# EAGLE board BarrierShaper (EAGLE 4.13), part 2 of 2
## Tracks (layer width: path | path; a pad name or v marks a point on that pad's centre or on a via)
+1.5V  (via drill 0.51, 0.71)
  Top 0.203: 100.26,51.76 IC3.93 | IC3.82 105.76,52.04 v105.28,51.31 | IC3.9 96.56,47.33 v96.65,47.24 | 100.26,38.54 IC3.33
  Top 0.305: IC16.2 47.5,67.06 48.26,67.06 R50.2 48.26,62.74 C49.+ 47.84,62.02 C52.2 50.16,59.05 v64.77,44.45 | v98.81,45.72 98.81,46.48 102.11,49.78 v102.11,50.04 | IC3.44 105.77,38 105.77,39.12 105.66,39.12 v105.28,39.37 | v100.84,39.37 100.84,39.12 100.26,38.54 | v100.58,51.44 100.26,51.76
  Bottom 0.305: v100.84,39.37 C55.2 101.09,40.64 102.62,40.64 | v105.28,39.37 105.16,39.62 C58.2 104.9,40.64 102.62,40.64 | v100.58,51.44 100.58,50.55 C63.2 101.09,50.04 v102.11,50.04 104.9,50.04 C61.2 v105.28,51.31 | 102.62,40.64 102.62,43.18 100.08,45.72 v98.81,45.72 98.04,45.72 98.04,46.99 C78.2 v96.65,47.24 95,47.24 91.44,43.69 79.5,43.69 78.74,44.45 v64.77,44.45
  pour Top (isolate 0.406): 40.01,100.97 40.01,70.48 53.98,70.48 53.98,100.97
+3.3V  (via drill 0.51, 0.71)
  Top 0.203: IC3.46 106.81,37.33 v106.81,39.24 | IC3.95 99.26,52.12 99.31,51.94 | IC3.18 96.68,42.83 v96.77,42.93 | 109.58,43.71 109.58,43.58 109.86,43.31 110.74,43.31 IC3.59 | IC3.80 106.76,52.5 107.06,52.2
  Top 0.305: IC16.3 50.04,68.07 51.31,68.07 C47.2 51.82,68.33 51.82,69.34 56.39,69.34 56.39,70.36 56.64,70.61 62.74,70.61 62.99,70.36 62.99,68.83 IC15.2 62.99,67.06 62.99,65.79 63.25,65.79 R49.2 C50.+ 64.01,62.99 65.79,62.99 C53.2 66.04,60.71 71.37,55.37 71.37,54.36 C72.2 71.37,53.59 71.37,53.09 IC2.4 71.88,51.05 71.88,50.04 78.23,43.69 v78.23,43.18 78.23,42.16 C71.2 78.23,41.66 78.23,40.39 IC1.3 78.23,38.35 78.23,37.34 78.49,37.34 79.5,36.32 79.5,35.31 IC1.7 | IC1.7 79.5,33.27 79.5,32.51 C64.2 78.99,32 76.45,32 75.69,32.77 v75.18,32.51 74.17,32.51 C1.2 | IC1.7 IC1.8 | v71.37,29.21 71.37,30.23 R1.2 | 106.68,47.24 v108.2,45.72 108.2,45.09 109.58,43.71 | R4.1 R3.1 v98.81,60.96 | 99.57,43.18 99.57,39.62 v99.19,39.37 99.26,39.01 99.26,38 IC3.31 | 99.57,43.18 97.54,45.21 v97.03,45.47 99.31,47.75 v99.31,51.18 99.31,51.94 | 106.68,47.24 103.63,47.24 99.57,43.18 | C6.1 150.11,84.07 150.11,83.06 150.62,82.55 150.62,81.53 IC5.27 150.62,81.03 150.62,79.5 122.68,51.56 v122.68,46.74 122.68,45.72 R5.2 122.68,44.45 122.68,43.69 R6.2 | 106.68,47.24 107.06,47.24 107.57,47.75 v107.57,51.44 107.57,51.69 107.06,52.2
  Bottom 0.203: C66.2 108.29,44.16
  Bottom 0.305: 73.15,30.99 74.68,32.51 v75.18,32.51 | v71.37,29.21 73.15,30.99 | 73.15,30.99 71.37,32.77 71.37,34.29 J1.4 | C67.2 107.7,39.37 107.19,39.37 v106.81,39.24 106.81,43.05 107.19,43.43 107.57,43.43 108.29,44.16 | C66.2 108.2,44.7 v108.2,45.72 108.71,45.97 109.47,46.74 v122.68,46.74 | v99.19,39.37 98.3,39.37 C68.2 | v99.31,51.18 98.81,51.56 98.3,51.56 C70.2 98.04,54.1 98.81,54.86 v98.81,60.96 | v96.77,42.93 96.77,43.69 C69.2 | v97.03,45.47 97.03,44.45 C69.2 | v78.23,43.18 93.22,43.18 94.23,44.2 96.52,44.2 C69.2 | C65.2 107.48,51.27 v107.57,51.44
  pour Top (isolate 0.406): 55.88,70.48 55.88,100.97 69.85,100.97 69.85,70.48
+5REF
  Top 0.254: R36.1 158.75,63.25 158.24,62.74 158.24,48.77 R33.1 158.24,47.75 158.24,43.94 150.88,36.58 150.88,34.54 150.62,34.29 150.88,34.04 150.88,32.77 | 154.18,24.13 151.89,26.42 151.89,28.7 R32.2 151.89,29.72 151.89,30.23 151.38,30.23 151.38,30.73 150.88,31.24 150.88,32.77 | 154.18,24.13 158.75,19.56 R35.1 | 154.18,24.13 158.24,28.19 158.24,29.97 R34.1 | 150.88,32.77 151.13,33.02 IC8.6
+5V  (via drill 0.51, 0.71)
  Top 0.254: C3.+ 103.89,100.33 103.89,97.54 C2.2 104.14,97.28 105.16,97.28 IC4.14 106.93,97.28 v114.3,97.28 | C51.2 81.03,62.23 C48.+ 79.25,62.74 79.5,62.74 79.5,64.26 R48.2 79.5,65.28 79.5,67.06 79.25,67.06 IC14.2 78.74,71.12 | C5.2 151.89,84.07 151.89,83.06 v152.15,82.8 152.4,82.55 152.4,81.53 IC5.24 152.4,81.03 v152.4,78.74 | 170.94,97.54 170.69,97.79 170.69,102.36 170.94,102.62 171.7,102.62 Q1.2 | 170.94,97.54 171.7,97.54 Q2.2 | v169.67,97.54 170.94,97.54 | C22.+ 113.28,8.89 113.28,10.41 C25.1 113.28,11.18 113.28,12.7 IC7.16 115.32,12.7 117.09,14.48 117.09,17.78 118.36,19.05 118.36,28.19 127.25,37.08 145.16,37.08 147.07,39.37 C21.+ 147.83,39.62 146.81,39.62 147.07,39.88 148.21,40.39 148.59,40.39 148.97,40.51 C26.1 149.35,41.4 149.35,41.91 IC9.3 149.35,42.67 149.35,44.7 v148.59,45.47 | v151.13,49.53 151.13,48.51 IC9.9
  Top 0.305: C3.+ 86.36,100.97 85.09,99.69
  Bottom 0.254: v169.67,97.54 154.94,82.8 v152.15,82.8 137.67,97.28 v114.3,97.28 | v148.59,45.47 148.59,46.99 v151.13,49.53 151.38,49.78 151.38,77.72 v152.4,78.74
  pour Top (isolate 0.406): 71.75,70.48 71.75,100.97 85.72,100.97 85.72,70.48
+7.5V  (via drill 0.51, 0.71)
  Top 0.254: IC12.7 165.61,12.7 165.61,15.24 C37.1 165.86,16.51 165.86,17.27 C36.+ 166.37,26.42 165.61,27.18 165.61,30.48 | IC8.7 C24.2 155.45,34.54 155.45,35.56 155.7,35.81 163.32,35.81 163.58,35.56 C32.+ | C32.+ 165.86,35.05 165.86,34.29 C33.1 165.61,33.02 165.61,30.48 | 165.61,30.48 IC11.7 | 165.61,48.26 165.61,50.8 C29.1 165.86,52.07 165.86,53.34 C28.+ 166.12,54.61 166.12,62.23 165.61,62.74 165.61,66.04 | 165.61,48.26 IC10.7 | C8.+ 167.64,88.39 C9.1 167.39,86.61 166.88,86.61 v166.88,84.07 166.88,83.82 IC6.7 | 165.61,66.04 165.61,68.58 C41.1 165.86,69.85 165.86,70.61 C40.+ v166.37,72.64 | 165.61,66.04 IC13.7 | 165.61,48.26 165.61,44.96 166.37,44.2 C32.+ | IC15.3 65.79,68.07 67.31,68.07 C46.2 67.82,68.33 v67.82,69.34 | C45.2 83.06,68.07 81.79,68.07 IC14.3 80.77,68.58 v82.8,69.6 | 140.46,147.57 D2.K+ | F1.2 140.46,144.53
  Top 0.305: 140.46,144.53 140.46,147.57 | C8.+ v147.32,88.9
  Bottom 0.254: v166.88,84.07 166.37,83.57 v166.37,72.64 | v67.82,69.34 79.25,69.34 v82.8,69.6 | v147.32,88.9 146.81,88.9
  Bottom 0.305: 140.34,142.37 F1.2 140.34,138.81 136.65,135.13 136.65,107.95 | v82.8,69.6 93.98,80.64 93.98,102.23 99.69,107.95 136.65,107.95 | 136.65,107.95 136.65,99.06 146.81,88.9
-7.5V  (via drill 0.51, 0.71)
  Top 0.203: D1.1 151.76,148.59 151.13,149.22 149.22,149.22 148.59,148.59 148.59,132.84 | C44.- 151.76,108.58 v138.43,95.25
  Top 0.254: PWR1.7 130.3,139.7 131.32,139.7 138.18,132.84 148.59,132.84 151.13,132.84 C44.- 152.15,132.08 | C39.- 160.53,8.89 C38.1 IC12.4 v164.59,10.16 | C34.1 IC11.4 | C35.- 160.53,26.67 C34.1 | v164.08,26.67 C34.1 | C43.- 161.29,61.72 161.8,62.23 C42.1 IC13.4 | C30.1 162.05,43.94 160.53,43.94 C31.- | C30.1 IC10.4 v164.59,45.72 | v160.27,50.04 158.75,51.56 158.75,61.47 159,61.72 160.02,61.72 C43.- | v164.08,43.94 163.07,43.94 C30.1 | v160.53,63.25 160.53,62.23 C43.-
  Bottom 0.254: v164.59,10.16 164.59,11.43 163.58,12.45 163.58,26.16 v164.08,26.67 163.83,26.92 163.83,29.97 163.58,30.23 163.58,43.43 v164.08,43.94 | v160.27,50.04 v164.59,45.72 | v138.43,95.25 138.94,95.25 151.13,83.06 151.13,81.28 161.54,70.87 161.54,64.26 v160.53,63.25
ADCS_CLK  (via drill 0.51)
  Top 0.203: v98.81,34.54 98.3,35.05 98.3,36.83 IC3.29 | IC7.12 v112.01,15.24
  Bottom 0.203: v112.01,15.24 112.01,21.34 v98.81,34.54
ADCS_CS  (via drill 0.51)
  Top 0.203: v96.77,35.81 96.77,36.7 IC3.26 | IC7.11 v115.19,15.88
  Bottom 0.203: v115.19,15.88 115.19,20.45 99.82,35.81 99.82,36.58 96.77,36.58 v96.77,35.81
ADCS_SDI
  Top 0.254: IC7.14 111,13.97 97.79,27.18 97.79,36.83 IC3.28
ADCS_SDO  (via drill 0.51)
  Top 0.203: v110.49,15.88 110.74,15.62 110.74,14.86 110.87,14.86 110.87,14.73 111,14.73 111,14.61 111.12,14.61 111.12,14.48 112.39,14.48 112.52,14.61 IC7.13 | v95.76,35.18 v95.76,38.35 | IC3.27 97.26,38.25 97.03,38.48 96.9,38.48 v96.39,38.99
  Bottom 0.203: v110.49,15.88 110.49,20.45 v95.76,35.18 | v95.76,38.35 v96.39,38.99
AGND  (via drill 0.51)
  Top 0.203: v103.53,39.32 104.57,38.81 104.9,38.48 105.16,38.48 105.28,38.35 105.28,37.34 105.28,37.33 IC3.43 | 151.76,133.99 D1.2 | IC3.30 98.76,38.4 98.68,38.48
  Top 0.254: v156.72,47.75 156.72,45.97 v157.23,45.47
  Bottom 0.203: v127.36,27.94 127.56,27.94 | v103.53,39.32 102.51,38.3 102.51,37.59 97.84,37.59 97.84,38.51 97.23,38.51 97.23,40.34 97.64,40.34 97.64,40.64 C68.1 | 89.22,38.2 89.31,38.2 89.71,38.2 90.32,38.81 90.32,39.83 90.02,40.13 90.02,40.74 91.85,42.57 96.01,42.57 96.52,42.06 97.03,42.06 97.06,42
  Bottom 0.254: v157.73,80.01 157.99,80.01 162.81,75.18 162.81,65.28 164.08,64.01 v164.59,64.01 | v159.77,52.07 156.72,49.02 v156.72,47.75 | v157.23,45.47 v159.26,45.47
  other vias: 155.96,82.55 48.01,12.19 48.01,17.27 48.01,22.35 48.01,32.51 48.01,37.59 48.01,42.67 82.42,37.97 97.84,42.37 48.26,27.03 106.55,48.26 96.65,50.29 112.39,43.18 127.36,31.75 109.22,39.37 100.97,46.35 103.5,48.9 114.3,57.78 137.79,62.23 133.99,69.85 133.99,81.28 119.38,100.97 110.49,88.9 88.9,66.04 70.48,65.41 53.34,65.41 38.73,65.41 51.44,5.08 69.22,18.41 104.78,17.14 142.88,4.45 142.88,29.84 136.53,42.55 146.05,57.15 163.19,76.2 156.84,77.47 163.83,104.78 163.83,118.11 146.69,118.11 93.98,53.98 93.98,35.56 111.76,38.1 48.01,47.75 146.69,45.09
  pour Top (isolate 0.254, rank 2): 35.56,154.94 187.96,154.94 187.96,0 110.49,0 102.87,17.14 72.39,17.14 64.77,0 35.56,0
  pour Bottom (isolate 0.254, rank 2): 35.56,0 187.96,0 187.96,154.94 35.56,154.94
DACF0  (via drill 0.51)
  Top 0.203: IC3.54 120.46,40.83 v120.52,40.77 | IC5.12 157.01,74.08 134.75,51.82 v134.75,50.93
  Bottom 0.203: v134.75,50.93 124.59,40.77 v120.52,40.77
DACF1  (via drill 0.51)
  Top 0.203: v132.33,50.16 156.34,74.17 156.34,74.93 IC5.11 | v106.43,46.1 106.81,45.72 106.81,45.47 107.95,44.2 109.6,42.55 109.6,41.53 109.8,41.33 IC3.55
  Bottom 0.203: v132.33,50.16 130.68,48.51 115.32,48.51 114.81,48.01 114.81,47.24 108.58,47.24 108.58,47.5 107.57,47.5 106.43,46.35 v106.43,46.1
DACF2  (via drill 0.51)
  Top 0.203: v150.24,77.85 150.37,77.85 151.26,76.96 155.45,76.96 155.7,76.71 155.7,75.82 IC5.10 | v144.4,75.44 137.79,68.83 137.03,67.94 120.27,51.18 119.38,51.18 119.38,46.23 119.25,46.1 119.25,45.59 v119.38,45.47 | IC3.56 113.84,41.83 v114.17,42.16
  Bottom 0.203: v150.24,77.85 146.81,77.85 v144.4,75.44 | v119.38,45.47 119,45.47 118.62,45.09 116.2,45.09 114.17,43.05 v114.17,42.16
DACF3  (via drill 0.51)
  Top 0.203: v112.52,45.09 114.17,46.74 114.94,46.74 115.44,46.23 115.44,45.47 113.92,43.94 | v107.7,42.55 107.7,42.16 108.2,42.16 108.2,38.73 108.46,38.48 109.22,38.48 109.22,37.97 | v149.61,50.29 v152.27,52.96 | v155.19,74.17 155.19,74.93 IC5.9 | IC3.57 112.94,42.33 113.54,42.93 113.54,43.56 113.92,43.94 | v118.75,41.91 115.95,41.91 113.92,43.94
  Bottom 0.203: v112.52,45.09 112.52,44.83 110.24,42.55 v107.7,42.55 | v149.61,50.29 149.35,50.04 149.35,48.9 148.46,48.9 147.32,47.62 132.08,47.62 123.83,39.37 120.02,39.37 119.38,40.01 119.38,41.27 v118.75,41.91 | v152.27,52.96 151.89,52.96 151.89,71.63 152.65,71.63 v155.19,74.17
DACF4  (via drill 0.51)
  Top 0.203: v124.08,47.75 128.91,47.75 129.79,48.64 130.56,48.64 131.57,49.66 131.57,50.67 154.43,73.53 154.43,74.93 IC5.8 | v115.7,47.75 115.19,47.75 114.68,47.24 114.05,47.24 113.16,46.35 111.51,46.35 IC3.65
  Bottom 0.203: v124.08,47.75 123.83,48.01 115.7,48.01 v115.7,47.75
DACF5  (via drill 0.51)
  Top 0.203: v130.81,50.04 130.81,50.55 153.8,73.53 153.8,74.93 IC5.7 | v116.46,49.78 115.7,49.02 115.7,48.9 114.55,47.75 112.01,47.75 IC3.68
  Bottom 0.203: v130.81,50.04 128.02,50.04 127.51,49.53 116.71,49.53 v116.46,49.78
DACF6  (via drill 0.51)
  Top 0.203: v128.91,49.28 153.16,73.53 153.16,74.93 IC5.6 | v114.94,49.28 113.92,48.26 112.14,48.26 IC3.69
  Bottom 0.203: v128.91,49.28 128.65,49.02 115.19,49.02 v114.94,49.28
DACF7  (via drill 0.51)
  Top 0.203: IC3.70 113.35,48.83 v118.24,53.72 | IC5.5 152.46,73.47 135.13,56.13 v131.06,56.13
  Bottom 0.203: v131.06,56.13 120.65,56.13 v118.24,53.72
DACF8  (via drill 0.51)
  Top 0.203: v147.83,72.64 148.08,72.9 151.13,72.9 151.89,73.66 151.89,74.93 IC5.4 | v114.55,53.34 114.55,50.93 112.9,49.28 111.51,49.28 IC3.71
  Bottom 0.203: v147.83,72.64 146.05,72.64 145.54,73.15 133.6,73.15 114.55,54.1 v114.55,53.34
DACF9  (via drill 0.51)
  Top 0.203: v146.81,73.41 150.88,73.41 151.13,73.66 151.13,74.93 IC5.3 | v113.79,52.32 113.79,50.93 112.65,49.78 111.51,49.78 IC3.72
  Bottom 0.203: v146.81,73.41 146.56,73.66 133.35,73.66 113.79,54.1 v113.79,52.32
DACF10  (via drill 0.51)
  Top 0.203: v150.37,74.17 150.37,74.93 IC5.2 | v109.22,50.04 109.22,50.29 110.24,50.29 IC3.73
  Bottom 0.203: v150.37,74.17 133.1,74.17 109.47,50.55 109.47,50.29 v109.22,50.04
DACF11  (via drill 0.51)
  Top 0.254: v123.7,51.31 123.7,51.82 147.32,75.44 IC5.1 | v112.27,50.8 111.51,50.8 IC3.74
  Bottom 0.254: v123.7,51.31 112.78,51.31 v112.27,50.8
DACF_CLK  (via drill 0.51)
  Top 0.203: IC5.28 148.84,81.28 117.35,49.78 v117.35,44.2 | IC3.53 111.69,40.33 112.52,39.5 v117.09,39.5
  Bottom 0.203: v117.35,44.2 117.35,39.75 v117.09,39.5
DACS_CLK
  Top 0.203: IC9.14 147.83,48.13 129.92,48.13 117.35,35.56 103,35.56 102.74,35.81 102.74,36.7 IC3.38
DACS_DATA  (via drill 0.51)
  Top 0.203: v105.28,46.1 102.23,43.05 102.23,37.97 IC3.37 | v112.14,52.07 112.52,52.45 112.52,53.21 113.92,54.61 v120.78,54.61 | v148.59,49.66 148.59,48.64 IC9.13
  Bottom 0.203: v105.28,46.1 105.92,46.74 105.92,46.86 106.3,46.86 107.44,48.01 108.33,48.01 108.46,48.13 108.46,48.51 108.58,48.51 108.58,48.77 109.98,48.77 109.98,48.64 110.11,48.51 110.49,48.51 111.38,49.4 111.38,51.82 111.51,51.82 111.51,51.94 111.76,51.94 111.76,52.07 v112.14,52.07 | v120.78,54.61 122.43,52.96 145.29,52.96 v148.59,49.66
DACS_~SYNC
  Top 0.203: IC9.2 148.46,41.91 148.46,41.66 148.34,41.66 148.34,41.53 146.94,41.53 140.84,47.62 130.05,47.62 117.47,35.05 102.49,35.05 101.73,35.81 101.73,36.7 IC3.36
DIG0  (via drill 0.51)
  Top 0.203: v75.69,40.13 71.88,43.94 70.61,43.94 67.31,40.64 58.42,40.64 R15.1B | v83.95,42.04 91.69,49.78 94.23,49.78 IC3.4
  Bottom 0.203: v75.69,40.13 78.49,40.13 78.99,39.62 81.53,39.62 v83.95,42.04
DIG1  (via drill 0.51)
  Top 0.203: v59.44,39.88 58.42,39.88 R15.2B | v67.31,54.1 68.58,55.37 v70.1,55.37 | v92.2,49.02 92.46,49.28 94.23,49.28 IC3.5
  Bottom 0.203: v59.44,39.88 59.44,46.23 v67.31,54.1 | v70.1,55.37 85.85,55.37 v92.2,49.02
DIG2  (via drill 0.51)
  Top 0.203: v77.34,29.97 74.42,27.05 73.15,27.05 72.9,27.3 68.96,27.3 61.98,34.29 61.98,35.94 59.31,38.61 58.8,38.61 58.8,38.73 58.67,38.73 58.67,38.86 58.42,38.86 R15.3B | v90.3,35.81 v92.84,38.35 | v93.34,41.78 94.11,41.78 IC3.20
  Bottom 0.203: v77.34,29.97 78.23,30.86 82.04,30.86 86.36,35.18 89.66,35.18 v90.3,35.81 | v92.84,38.35 92.84,41.27 v93.34,41.78
DIG3  (via drill 0.51)
  Top 0.203: v77.34,28.83 76.83,28.83 74.55,26.54 73.03,26.54 72.77,26.8 68.83,26.8 61.47,34.16 61.47,35.81 59.31,37.97 58.42,37.97 R15.4B | v91.44,35.81 v93.98,38.35 | v96.27,41.27 95.5,41.27 IC3.21
  Bottom 0.203: v77.34,28.83 78.87,30.35 82.17,30.35 86.49,34.67 89.79,34.67 90.17,35.05 90.68,35.05 v91.44,35.81 | v93.98,38.35 93.98,38.99 v96.27,41.27
DIG4  (via drill 0.51)
  Top 0.203: v57.81,36.98 57.81,19.81 R16.1B | v65.23,56.39 67.06,58.22 v67.06,58.32 | v71.22,58.73 85.04,44.91 v85.04,44.5 | v90.83,40.44 91.24,40.44 91.64,40.84 94.08,40.84 IC3.22 | v90.22,44.5 86.87,41.15 v86.87,39.52 86.87,39.5
  Bottom 0.203: v57.81,36.98 57.71,37.08 57.71,48.87 v65.23,56.39 | v67.06,58.32 67.46,58.73 v71.22,58.73 | v85.04,44.5 85.04,44.45 90.22,44.45 v90.22,44.5 | v86.87,39.52 88.09,38.3 88.09,37.59 91.03,37.59 91.03,38.51 91.14,38.61 91.14,40.13 v90.83,40.44
DIG5
  Top 0.203: IC3.23 94.23,40.39 91.95,40.39 75.69,24.13 60.96,24.13 60.33,23.5 60.33,19.68 59.45,18.82 R16.2B
DIG6
  Top 0.203: IC3.24 94.23,39.88 92.2,39.88 75.82,23.5 61.59,23.5 60.96,22.86 60.96,19.05 59.92,18.02 R16.3B
DIG7
  Top 0.203: IC3.25 94.23,39.37 92.46,39.37 75.95,22.86 62.23,22.86 61.59,22.23 61.59,18.41 60.4,17.21 R16.4B
N$1  (via drill 0.51)
  Top 0.203: v80.77,42.16 82.17,42.16 83.06,41.27 84.45,41.27 91.19,48.01 92.33,48.01 93.15,48.83 IC3.6
  Top 0.254: v80.77,42.16 80.77,40.39 IC1.1 | v71.12,42.42 67.31,38.61 67.31,36.32 67.06,36.07 67.06,35.81 66.29,35.81 66.29,35.56 J1.8
  Bottom 0.254: v80.77,42.16 80.26,42.67 78.99,42.67 78.23,41.91 71.63,41.91 v71.12,42.42
N$2  (via drill 0.51)
  Top 0.203: v81.66,41.27 82.3,40.64 84.45,40.64 91.31,47.5 92.58,47.5 93.42,48.33 IC3.7
  Top 0.254: v79.76,41.4 79.5,41.4 79.5,40.39 IC1.2
  Bottom 0.203: v81.66,41.27 80.14,41.27 v79.76,41.4
  Bottom 0.254: v79.76,41.4 68.33,41.4 66.29,39.37 66.29,38.1 J1.7
N$3  (via drill 0.51)
  Top 0.203: v84.84,36.2 92.46,43.81 94.11,43.81 IC3.16 | 78.11,36.32 v78.11,36.2
  Top 0.254: IC1.6 78.23,35.31 78.23,36.32 78.11,36.32 76.2,36.32 75.18,37.34 74.17,37.34 J1.1
  Bottom 0.203: v84.84,36.2 84.84,36.58 78.11,36.58 v78.11,36.2
N$4  (via drill 0.51)
  Top 0.203: v81.79,35.43 85.22,35.43 85.6,35.81 85.6,36.32 92.58,43.31 94.11,43.31 IC3.17
  Top 0.254: v75.69,33.78 76.71,33.78 IC1.5
  Bottom 0.203: v81.79,35.43 81.03,35.43 77.47,31.88 75.95,31.88 75.88,31.94
  Bottom 0.254: v75.69,33.78 75.69,33.27 76.2,32.77 76.2,32.26 75.88,31.94 72.14,28.19 67.82,28.19 61.72,34.29 61.72,35.81 62.23,36.32 62.23,37.08 62.99,37.08 J1.9
N$5  (via drill 0.51)
  Top 0.203: v114.68,45.85 113.16,44.32 112.27,44.32 111.78,43.83 IC3.60 | v116.2,45.85 116.08,45.59 v116.08,43.18
  Top 0.254: v116.08,43.18 R6.1
  Bottom 0.203: v116.2,45.85 v114.68,45.85 | 109.73,37.08 114.94,37.08 116.08,38.23 v116.08,43.18
  Bottom 0.254: 109.73,37.08 76.71,37.08 74.42,39.37 71.37,39.37 71.37,38.1 J1.3
N$6  (via drill 0.51)
  Top 0.203: v90.93,45.97 90.42,45.97 84.58,40.13 83.19,40.13 v82.3,39.24 | v72.26,40.26 71.37,40.26 69.6,38.48 69.09,38.48 69.09,37.85 J1.5 | IC3.8 96.09,47.83 96.27,48.01 v96.27,48.9
  Top 0.254: R1.1 70.87,32.77 70.87,33.78 69.85,33.78 69.85,36.07 69.6,36.32 69.6,36.58 68.83,36.58 68.83,36.83 J1.5
  Bottom 0.203: v96.27,48.9 94.74,48.9 92.96,47.12 92.96,45.97 v90.93,45.97 | v82.3,39.24 82.3,39.12 79.38,39.12 79.38,38.35 77.22,38.35 76.96,38.61 75.82,38.61 75.82,38.86 75.56,38.86 75.56,39.24 75.18,39.24 75.18,39.5 74.93,39.5 74.93,39.88 72.26,39.88 v72.26,40.26
N$7  (via drill 0.51)
  Top 0.203: v89.53,42.04 92.84,45.34 94.11,45.34 IC3.13 | v89.53,39.12 89.03,39.12 86.36,36.45 v86.36,35.94 | v73.53,27.81 70.74,27.81 v69.47,29.08 | v67.18,32.38 R2.2
  Top 0.254: R2.2 68.83,32.77 68.83,34.29 J1.6
  Bottom 0.203: v89.53,39.12 v89.53,42.04 | v86.36,35.94 86.36,35.81 81.92,31.37 77.09,31.37 v73.53,27.81 | v69.47,29.08 69.47,30.1 v67.18,32.38
N$8  (via drill 0.51)
  Top 0.203: v120.14,50.42 120.65,49.91 R5.1 | v109.22,48.01 109.09,47.88 109.09,44.96 109.73,44.32 110.11,44.32 IC3.61
  Bottom 0.203: v120.14,50.42 120.14,50.8 115.7,50.8 115.7,50.04 114.55,50.04 112.52,48.01 v109.22,48.01
N$9  (via drill 0.51)
  Top 0.203: v92.2,46.74 92.33,46.86 94.11,46.86 IC3.10 | v70.99,57.15 v73.53,54.61 | v68.2,57.15 63.63,52.58 63.63,51.56 66.17,49.02 68.2,49.02 69.09,48.13 69.09,47.88 69.22,47.75 70.1,47.75 IC2.3
  Bottom 0.203: v92.2,46.74 84.2,54.74 73.53,54.86 v73.53,54.61 | v68.2,57.15 v70.99,57.15
N$10
  Top 0.254: R4.2 95.5,58.67 95.5,57.66 96.77,56.39 96.77,53.85 IC3.100
N$11
  Top 0.254: R3.2 97.28,58.67 97.28,53.85 IC3.99
N$12  (via drill 0.51)
  Top 0.254: R33.2 IC10.2 v164.59,48.26 | v168.4,44.45 R37.1
  Bottom 0.254: v164.59,48.26 v168.4,44.45
N$13  (via drill 0.51)
  Top 0.254: R36.2 IC13.2 v164.59,66.04 | v168.4,62.23 R40.1
  Bottom 0.254: v164.59,66.04 v168.4,62.23
N$14
  Top 0.254: IC13.6 R44.1
N$15
  Top 0.254: R40.2 172.21,62.74 172.21,64.26 R44.2 172.47,65.02 175.26,65.02 J7.CONDUCTOR
N$16
  Top 0.254: IC10.6 R41.1
N$17  (via drill 0.51, 0.71)
  Top 0.254: IC9.6 151.13,41.91 C27.1 151.38,40.64 v152.4,40.64 | v146.05,33.02 IC8.3
  Bottom 0.254: v152.4,40.64 152.4,39.37 v146.05,33.02
N$18
  Top 0.254: R37.2 172.21,44.96 172.21,46.48 R41.2 172.47,47.24 175.26,47.24 J4.CONDUCTOR
N$19  (via drill 0.51)
  Top 0.254: v160.53,28.96 160.53,29.21 IC11.3 | v150.88,43.94 150.62,43.69 150.62,42.67 IC9.5
  Bottom 0.254: v160.53,28.96 160.53,34.29 v150.88,43.94
N$20
  Top 0.254: DIGO6.TP 45.72,16 49.78,16 Q9.1
N$21  (via drill 0.51)
  Top 0.254: R34.2 IC11.2 v164.59,30.48 | v168.4,26.67 R38.1
  Bottom 0.254: v164.59,30.48 v168.4,26.67
N$22
  Top 0.254: IC11.6 R42.1
N$23
  Top 0.254: R38.2 172.21,27.18 172.21,28.7 R42.2 172.47,29.46 175.26,29.46 J5.CONDUCTOR
N$24  (via drill 0.51)
  Top 0.254: v149.86,45.47 150.88,46.48 150.88,47.24 150.62,47.24 150.62,48.01 IC9.10 | v160.53,11.18 160.53,11.43 IC12.3
  Bottom 0.254: v149.86,45.47 150.62,45.47 161.04,35.05 161.04,29.72 163.07,27.69 163.07,13.72 v160.53,11.18
N$25  (via drill 0.51)
  Top 0.254: R35.2 IC12.2 v164.59,12.7 | v168.4,8.89 R39.1
  Bottom 0.254: v164.59,12.7 v168.4,8.89
N$26
  Top 0.254: IC12.6 R43.1
N$27
  Top 0.254: R39.2 172.21,9.4 172.21,10.92 R43.2 172.47,11.68 175.26,11.68 J6.CONDUCTOR
N$28
  Top 0.254: C4.2 157.23,84.07 157.23,83.06 156.97,82.8 156.97,81.53 IC5.17
N$29  (via drill 0.51)
  Top 0.254: v156.46,79.76 156.46,81.03 IC5.18 | v161.04,84.07 161.04,84.33 160.27,84.33 160.27,84.58 160.02,84.58 R17.2
  Bottom 0.254: v156.46,79.76 156.46,80.26 160.27,84.07 v161.04,84.07
N$30  (via drill 0.51)
  Top 0.254: v154.43,79.76 154.43,81.03 IC5.21 | v160.78,85.34 156.21,85.34 156.21,85.09 155.96,85.09 155.96,84.84 R18.2
  Bottom 0.254: v154.43,79.76 155.19,79.76 v160.78,85.34
N$31
  Top 0.254: IC6.3 R19.2 159.77,82.55 159.51,82.3 159.51,80.52 157.73,78.74 154.18,78.74 153.42,79.5 153.42,80.26 153.67,80.26 153.67,81.03 IC5.22
N$32
  Top 0.254: IC5.23 153.16,81.53 153.16,82.8 153.42,83.06 153.42,84.07 C7.2
N$33
  Top 0.254: R20.2 169.67,77.98 169.67,78.74 R21.1 169.16,79.5 167.89,79.5 165.86,81.53 165.86,83.82 IC6.2
N$34
  Top 0.254: IC6.6 R22.1
N$35
  Top 0.254: R21.2 171.7,79.5 172.72,79.5 173.48,80.26 173.48,82.04 R22.2 J3.CONDUCTOR
N$36  (via drill 0.51, 0.71)
  Top 0.254: v149.86,46.74 149.86,48.01 IC9.11 | v160.53,46.74 161.29,46.74 161.29,46.99 IC10.3
  Bottom 0.254: v149.86,46.74 v160.53,46.74
N$37
  Top 0.254: R31.2 R32.1 149.86,30.99 150.37,31.5 150.37,33.78 149.86,34.29 IC8.2
N$38
  Top 0.254: R23.1 126.75,3.3 129.54,3.3 ANS1.TP
N$39
  Top 0.254: C19.+ 112.01,18.54 112.01,17.53 C18.2 112.52,16.76 112.52,16.51 IC7.10
N$40
  Top 0.254: IC7.9 113.54,17.27 113.54,18.8 C23.2 113.54,19.3 113.54,21.08 113.28,21.34 112.27,21.34 C20.+
N$41  (via drill 0.51)
  Top 0.254: v157.23,61.47 157.73,60.96 157.73,52.07 149.86,44.2 149.86,42.67 IC9.4 | v160.53,64.64 IC13.3
  Bottom 0.254: v157.23,61.47 v160.53,64.64
N$42
  Top 0.254: IC7.8 118.87,17.27 118.87,25.4 123.19,29.72 124.21,29.72 R30.2 C11.2
N$43
  Top 0.254: IC7.7 120.4,16.51 122.94,19.05 122.94,25.65 123.19,25.91 124.21,25.91 R29.2 C13.2
N$44  (via drill 0.51)
  Top 0.203: v117.35,13.59 117.73,13.59 117.73,15.88 IC7.6 | v120.14,17.4 120.65,17.4 122.43,19.18 122.43,25.78 123.19,26.54 v123.19,28.57 | v125.35,33.02 125.35,25.15 125.22,25.15 125.22,24.51 124.84,24.51 C15.2
  Top 0.254: C15.2 R28.2
  Bottom 0.203: v117.35,13.59 117.35,14.61 v120.14,17.4 | v123.19,28.57 123.19,30.86 v125.35,33.02
N$45
  Top 0.254: IC7.5 120.4,15.24 122.94,17.78 122.94,18.03 123.19,18.29 124.21,18.29 R27.2 C17.2
N$46
  Top 0.203: IC7.4 R26.2
  Top 0.254: R26.2 C10.2
N$47
  Top 0.254: IC7.3 122.17,13.97 123.19,12.95 124.21,12.95 C12.2 R25.2
N$48
  Top 0.203: IC7.2 120.78,13.34 120.9,13.21 120.9,12.83 123.44,10.29 123.44,9.65 123.57,9.53 124.08,9.53 C14.2
  Top 0.254: C14.2 R24.2
N$49
  Top 0.254: R23.2 C16.2 124.21,5.33 123.19,5.33 122.94,5.59 122.94,10.16 120.4,12.7 IC7.1
N$50
  Top 0.254: R24.1 126.75,7.11 129.54,7.11 ANS2.TP
N$51
  Top 0.254: R25.1 126.75,10.92 129.54,10.92 ANS3.TP
N$52
  Top 0.254: R26.1 126.75,14.73 129.54,14.73 ANS4.TP
N$53
  Top 0.254: R27.1 126.75,18.54 129.54,18.54 ANS5.TP
N$54
  Top 0.254: R28.1 126.75,22.35 129.54,22.35 ANS6.TP
N$55
  Top 0.254: R29.1 126.75,26.16 129.54,26.16 ANS7.TP
N$56
  Top 0.254: R30.1 126.75,29.97 129.54,29.97 ANS8.TP
N$57
  Top 0.254: DIGO7.TP 45.72,10.92 49.78,10.92 Q10.1
N$58
  Top 0.254: DIGO0.TP 45.72,46.48 49.78,46.48 Q3.1
N$59
  Top 0.254: DIGO1.TP 45.72,41.4 49.78,41.4 Q4.1
N$60
  Top 0.254: DIGO2.TP 45.72,36.32 49.78,36.32 Q5.1
N$61
  Top 0.254: DIGO3.TP 45.72,31.24 49.78,31.24 Q6.1
N$62
  Top 0.254: R13.1A 118.87,93.47 117.09,93.47 IC4.8
N$63
  Top 0.254: R13.2A 118.87,92.46 118.36,92.46 118.36,92.2 117.09,92.2 IC4.7
N$64
  Top 0.254: R14.4A 103.63,92.2 103.63,93.22 103.89,93.47 105.16,93.47 IC4.17
N$65
  Top 0.254: R13.3A 118.87,91.69 118.36,91.69 118.36,90.93 117.09,90.93 IC4.6
N$66
  Top 0.254: R14.2A 104.14,90.42 105.41,90.42 105.66,90.68 IC4.19
N$67
  Top 0.254: R14.3A 104.14,91.19 104.39,91.19 104.39,91.44 104.65,91.44 104.65,91.69 105.41,91.69 105.66,91.95 IC4.18
N$68
  Top 0.254: R14.1A 104.14,89.66 105.16,89.66 IC4.20
N$69
  Top 0.254: R13.4A 119.13,90.68 119.13,89.66 117.09,89.66 IC4.5
N$70  (via drill 0.51)
  Top 0.254: J2.2 178.05,118.11 R7.2 172.47,118.11 148.08,93.73 123.44,93.73 v122.94,94.23 | v108.97,96.01 106.93,96.01 IC4.15
  Bottom 0.254: v108.97,96.01 112.27,92.71 121.41,92.71 v122.94,94.23
N$71  (via drill 0.51)
  Top 0.254: v113.54,93.73 112.52,94.74 106.93,94.74 IC4.16 | v122.94,95.5 124.21,94.23 147.83,94.23 168.4,114.81 v168.4,115.32
  Bottom 0.254: v113.54,93.73 114.05,93.22 120.65,93.22 v122.94,95.5 | v168.4,115.32 179.83,115.32 180.09,115.57 180.09,116.84 J2.3
N$72
  Top 0.254: IC4.13 106.93,98.55 108.46,98.55 108.71,98.81 108.71,100.84 X1.1
N$73
  Top 0.254: IC4.12 115.32,98.55 114.05,98.55 113.79,98.81 113.79,100.84 X1.2
N$74
  Top 0.254: R9.1 176.78,103.63 175.26,103.63 Q1.3
N$75
  Top 0.254: R9.2 179.32,103.63 180.59,103.63 LED1.P$1
N$76
  Top 0.254: R10.1 176.78,98.55 175.26,98.55 Q2.3
N$77
  Top 0.254: R10.2 179.32,98.55 180.59,98.55 LED2.P$1
N$78
  Top 0.254: R8.2 117.86,97.28 117.09,97.28 IC4.11
N$79
  Top 0.254: R11.1A 118.87,87.63 118.87,88.39 117.09,88.39 IC4.4
N$80
  Top 0.254: R11.2A 118.87,86.87 117.09,86.87 IC4.3
N$81
  Top 0.254: R12.4A 104.14,87.63 104.14,88.39 105.16,88.39 IC4.21
N$82
  Top 0.254: R12.3A 104.14,86.87 105.16,86.87 IC4.22
N$83
  Top 0.254: R12.2A 104.14,85.85 105.16,85.85 IC4.23
N$84
  Top 0.254: R12.1A 103.89,85.09 103.89,84.58 105.16,84.58 IC4.24
N$85
  Top 0.254: R11.3A 118.87,85.85 117.09,85.85 IC4.2
N$86
  Top 0.254: R11.4A 119.13,85.09 119.13,84.58 117.09,84.58 IC4.1
N$87
  Top 0.254: DIGO4.TP 45.72,26.16 49.78,26.16 Q7.1
N$88
  Top 0.254: DIGO5.TP 45.72,21.08 49.78,21.08 Q8.1
N$89
  Top 0.254: Q3.3 51.82,44.96 53.09,44.96 56.39,41.66 56.39,40.64 R15.1A
N$90
  Top 0.254: Q4.3 51.82,39.88 55.88,39.88 R15.2A
N$91
  Top 0.254: Q10.3 51.82,9.4 52.83,9.4 56.39,12.95 56.39,17.02 R16.4A
N$92
  Top 0.254: Q9.3 51.82,14.48 52.83,14.48 54.36,16 54.36,17.27 55.12,18.03 55.88,18.03 R16.3A
N$93
  Top 0.254: Q8.3 51.82,19.56 52.83,19.56 53.59,18.8 55.88,18.8 R16.2A
N$94
  Top 0.254: Q7.3 51.82,24.64 52.83,24.64 56.39,21.08 56.39,19.81 R16.1A
N$95
  Top 0.254: Q6.3 51.82,29.72 52.83,29.72 56.39,33.27 56.39,38.1 R15.4A
N$96
  Top 0.254: Q5.3 51.82,34.8 52.83,34.8 54.36,36.32 54.36,38.1 55.12,38.86 55.88,38.86 R15.3A
N$97
  Top 0.254: R49.1 61.21,65.53 59.94,65.53 R46.2 59.69,67.31 59.94,67.31 IC15.1
N$98
  Top 0.254: 44.45,65.02 45.97,65.02 R50.1 | 44.45,65.02 44.2,65.02 R47.2 | 44.45,65.02 IC16.1
N$99
  Top 0.305: PWR1.5 130.3,121.41 134.37,121.41 136.91,118.87 F1.1
N$100
  Top 0.203: AC1.TP 67.31,113.03 PWR1.3
N$101
  Top 0.203: AC2.TP 67.44,133.99 PWR1.2
N$102
  Top 0.203: GND.TP 67.18,149.22 PWR1.1
N$103
  Top 0.254: R48.1 77.22,65.02 75.95,65.02 R45.2 75.69,65.28 75.69,66.8 76.2,66.8 IC14.1
N$104
  Top 0.254: R7.1 175.77,120.14 177.8,120.14 J2.1
N$105
  Top 0.203: IN1.TP 9.53,111.76 10.16,111.12 10.16,108.58 10.79,107.95 IC18.3
N$106
  Top 0.203: IN2.TP 9.53,107.31 10.16,106.68 IC18.4
N$107
  Top 0.203: IN3.TP 9.53,102.87 10.16,103.5 10.16,104.78 10.79,105.41 IC18.5
N$108
  Top 0.203: IN4.TP 10.16,98.42 10.79,99.06 10.79,103.5 11.43,104.14 IC18.6
N$109
  Top 0.203: IN5.TP 9.53,45.72 10.16,45.09 10.16,42.55 10.79,41.91 IC19.3
N$110
  Top 0.203: +5V-IN.TP 16.51,114.94 15.24,113.67 C74.+
  Top 0.254: C74.+ 14.73,112.78 13.72,112.78 C73.2 13.46,111.76 13.46,110.74 IC18.1
N$111
  Top 0.203: IC18.8 13.97,101.6 14.61,102.23 14.61,109.22 | COM-IN.TP C73.1 11.43,111.76 10.79,111.12 10.79,109.86 11.43,109.22 IC18.2 14.61,109.22 | 14.61,109.22 15.24,109.22 17.78,111.76 C74.-
  Top 0.254: C74.- 17.53,113.54
  pour Top (isolate 0.254): 1.27,90.17 1.27,121.54 19.68,121.54 19.68,112.39 16.51,109.22 16.51,102.87 11.43,97.79 11.43,90.17
N$112
  Top 0.203: IC18.14 24.77,107.95 25.4,108.58 25.4,111.12 26.04,111.76 OUT1.TP
N$113
  Top 0.203: IC18.13 24.13,106.68 24.77,107.31 OUT2.TP
N$114
  Top 0.203: IC18.12 24.77,105.41 25.4,104.78 25.4,103.5 26.04,102.87 OUT3.TP
N$115
  Top 0.203: IC18.11 24.13,104.14 24.77,103.5 24.77,99.06 25.4,98.42 OUT4.TP
N$116
  Top 0.203: C76.2 22.23,111.12 IC18.16 21.59,110.49 19.68,108.58 C75.+ 18.41,99.06 17.78,98.42 +5V-OUT.TP
N$117
  Top 0.203: COM-OUT.TP 22.86,96.52
  pour Top (isolate 0.254): 20.95,121.54 20.95,111.12 19.05,109.22 19.05,102.87 13.34,97.16 13.34,90.17 34.29,90.17 34.29,121.54
N$118
  Top 0.203: IN+.TP 6.35,142.24 6.99,142.88 R51.1
N$119
  Top 0.203: IN-.TP 8.89,133.99
  pour Top (isolate 0.254, rank 2): 1.27,147.83 14.61,147.83 14.61,129.92 1.27,129.92
N$120
  Top 0.203: IC17.2 10.79,139.06 10.03,139.83 R51.2
N$121
  Top 0.203: R52.2 22.23,140.97 21.59,141.6 IC17.8 | COM-IN1.TP 24.77,143.51 24.13,142.88 C77.2
  Top 0.254: R52.2 22.86,140.46 23.62,140.46 C77.2
N$122
  Top 0.203: IC17.6 21.59,136.53 22.23,137.16 | 22.23,137.16 R52.1 | 22.23,137.16 22.86,136.53 24.26,136.53 25.02,135.76 COM-IN2.TP
N$123
  Top 0.203: 26.67,138.43 COM-IN3.TP
  pour Top (isolate 0.254): 17.14,147.83 34.29,147.83 34.29,129.92 17.14,129.92
N$124
  Top 0.203: IN6.TP 9.53,41.27 10.16,40.64 IC19.4
N$125
  Top 0.203: IN7.TP 9.53,36.83 10.16,37.47 10.16,38.73 10.79,39.37 IC19.5
N$126
  Top 0.203: IN8.TP 10.16,32.38 10.79,33.02 10.79,37.47 11.43,38.1 IC19.6
N$127
  Top 0.203: +5V-IN1.TP 16.51,48.9 15.24,47.62 C54.+
  Top 0.254: C54.+ 14.73,46.74 13.72,46.74 C56.2 13.46,45.72 13.46,44.7 IC19.1
N$128
  Top 0.203: IC19.8 13.97,35.56 14.61,36.2 14.61,43.18 | COM-IN4.TP C56.1 11.43,45.72 10.79,45.09 10.79,43.81 11.43,43.18 IC19.2 14.61,43.18 | 14.61,43.18 15.24,43.18 17.78,45.72 C54.-
  Top 0.254: C54.- 17.53,47.5
  pour Top (isolate 0.254): 1.27,24.13 1.27,55.5 19.68,55.5 19.68,46.35 16.51,43.18 16.51,36.83 11.43,31.75 11.43,24.13
N$129
  Top 0.203: IC19.14 24.77,41.91 25.4,42.55 25.4,45.09 26.04,45.72 OUT5.TP
N$130
  Top 0.203: IC19.13 24.13,40.64 24.77,41.27 OUT6.TP
N$131
  Top 0.203: IC19.12 24.77,39.37 25.4,38.73 25.4,37.47 26.04,36.83 OUT7.TP
N$132
  Top 0.203: IC19.11 24.13,38.1 24.77,37.47 24.77,33.02 25.4,32.38 OUT8.TP
N$133
  Top 0.203: C59.2 22.23,45.09 IC19.16 21.59,44.45 19.68,42.55 C57.+ 18.41,33.02 17.78,32.38 +5V-OUT1.TP
N$134
  Top 0.203: COM-OUT1.TP 22.86,30.48
  pour Top (isolate 0.254): 20.95,55.5 20.95,45.09 19.05,43.18 19.05,36.83 13.34,31.11 13.34,24.13 34.29,24.13 34.29,55.5
N$135
  Top 0.203: IN+1.TP 6.35,76.2 6.99,76.83 R54.1
N$136
  Top 0.203: IN-1.TP 8.89,67.94
  pour Top (isolate 0.254, rank 2): 1.27,81.79 14.61,81.79 14.61,63.88 1.27,63.88
N$137
  Top 0.203: IC20.2 10.79,73.03 10.03,73.79 R54.2
N$138
  Top 0.203: R53.2 22.23,74.93 21.59,75.56 IC20.8 | COM-IN5.TP 24.77,77.47 24.13,76.83 C60.2
  Top 0.254: R53.2 22.86,74.42 23.62,74.42 C60.2
N$139
  Top 0.203: IC20.6 21.59,70.48 22.23,71.12 | 22.23,71.12 R53.1 | 22.23,71.12 22.86,70.48 24.51,70.48 24.89,70.1 COM-IN6.TP
N$140
  Top 0.203: 26.67,72.39 COM-IN7.TP
  pour Top (isolate 0.254): 17.14,81.79 34.29,81.79 34.29,63.88 17.14,63.88
S$1
  Top 0.203: 0,0.64 0,0 0.64,0
S$2
  Bottom 0.203: 0,0.64 0,0 0.64,0
S$3
  Top 0.203: 187.32,0 187.96,0 187.96,0.64
S$4
  Bottom 0.203: 187.32,0 187.96,0 187.96,0.64
S$5
  Top 0.203: 187.96,154.31 187.96,154.94 187.32,154.94
S$6
  Bottom 0.203: 187.96,154.31 187.96,154.94 187.32,154.94
S$7
  Top 0.203: 0.64,154.94 0,154.94 0,154.31
S$8
  Bottom 0.203: 0.64,154.94 0,154.94 0,154.31
USB0
  Top 0.254: R11.4B 120.9,85.09 120.9,62.23 111,52.32 111,51.31 IC3.75
USB1  (via drill 0.51)
  Top 0.203: v108.71,54.86 108.71,53.85 IC3.76 | R11.3B 122.32,85.96 122.56,85.72 v122.56,69.85
  Bottom 0.203: v122.56,69.85 122.56,68.58 v108.71,54.86
USB2  (via drill 0.51)
  Top 0.203: v123.57,68.96 123.57,86.36 123.06,86.87 121.16,86.87 R11.2B | v109.22,51.56 108.71,51.56 108.2,52.07 108.2,52.83 IC3.77
  Bottom 0.203: v123.57,68.96 109.47,54.86 109.47,51.56 v109.22,51.56
USB3
  Top 0.203: R11.1B 120.4,87.78 120.29,87.78 119.18,88.9 114.4,88.9 114.3,88.8 114.3,81.86 119.13,77.04 119.13,66.6 107.8,55.27 107.8,54.05 IC3.78
USB4  (via drill 0.51)
  Top 0.203: v102.36,62.48 102.11,62.74 102.11,84.96 R12.1B | v107.19,57.02 107.31,56.9 107.31,53.98 IC3.79
  Bottom 0.203: v102.36,62.48 102.49,59.94 104.14,58.42 105.16,57.78 106.43,57.78 v107.19,57.02
USB5  (via drill 0.51)
  Top 0.203: v100.71,85.98 101.6,85.98 R12.2B | v102.87,83.82 102.62,83.57 102.62,63.88 v103.12,63.37 | v104.78,59.31 104.78,53.98 IC3.84
  Bottom 0.203: v102.87,83.82 v100.71,85.98 | v103.12,63.37 103.12,60.71 v104.78,59.31
USB6  (via drill 0.51)
  Top 0.203: v101.22,62.1 99.95,63.12 99.95,86.36 100.33,86.74 101.6,86.74 R12.3B | v104.01,57.4 104.27,57.15 104.27,53.98 IC3.85
  Bottom 0.203: v104.01,57.4 101.85,59.44 101.22,60.07 v101.22,62.1
USB7  (via drill 0.51)
  Top 0.203: v100.71,87.5 101.6,87.5 R12.4B | v103.5,56.01 103.76,55.75 103.76,53.98 IC3.86
  Bottom 0.203: v100.71,87.5 100.71,87.12 99.95,86.36 99.95,62.23 100.46,61.72 100.46,59.05 v103.5,56.01
USB8  (via drill 0.51)
  Top 0.203: v120.65,89.92 120.65,90.68 R13.4B | v106.55,59.31 105.79,58.55 105.79,57.15 106.55,56.39 v106.55,55.63 | IC3.87 103.25,52.7 103.25,52.32 v102.74,51.82
  Bottom 0.203: v120.65,89.92 105.92,75.18 105.92,62.23 106.55,61.59 v106.55,59.31 | v102.74,51.82 v106.55,55.63
USB9  (via drill 0.51)
  Top 0.203: v102.23,88.65 102.23,89.41 R14.1B | v104.9,60.45 104.9,60.33 104.65,60.07 104.01,60.07 104.01,58.55 102.74,57.28 102.74,53.98 IC3.88
  Bottom 0.203: v102.23,88.65 102.23,85.6 104.9,82.93 v104.9,60.45
USB10  (via drill 0.51)
  Top 0.203: v120.52,88.65 120.65,88.77 120.78,88.77 121.67,89.66 121.67,91.44 121.28,91.57 R13.3B | v103.5,50.93 102.23,50.93 101.85,51.44 101.85,52.07 102.26,52.48 IC3.89
  Bottom 0.203: v120.52,88.65 120.02,88.65 106.43,75.06 106.43,62.36 107.06,61.72 107.06,59.94 107.95,59.05 107.95,54.99 107.19,54.99 107.06,54.86 107.06,54.61 105.03,52.58 103.5,51.31 v103.5,50.93
USB11  (via drill 0.51)
  Top 0.203: v105.54,56.26 105.28,56.52 105.28,58.67 105.79,59.18 v105.79,61.21 | v100.84,90.3 101.6,90.3 R14.2B | IC3.90 101.76,54.77 v101.98,54.99
  Bottom 0.203: v101.98,54.99 104.27,54.99 v105.54,56.26 | v105.79,61.21 105.41,61.59 105.41,83.06 102.74,85.72 102.74,88.01 103,88.27 103,89.03 101.73,90.3 v100.84,90.3
USB12  (via drill 0.51)
  Top 0.203: IC3.91 101.26,54.44 101.09,54.61 101.09,58.17 110.74,67.82 111.76,67.82 v117.86,73.91 | R13.2B 121.52,92.47 122.17,91.82 122.17,88.65 v124.46,86.36
  Bottom 0.203: v117.86,73.91 117.86,74.04 124.46,80.64 v124.46,86.36
USB13  (via drill 0.51)
  Top 0.203: v99.95,89.53 99.95,89.92 100.08,90.04 100.08,90.81 100.2,90.81 100.2,90.93 100.33,90.93 100.33,91.06 101.35,91.06 101.35,91.19 101.6,91.19 R14.3B | IC3.92 100.76,54.31 100.08,54.99 v100.08,56.13
  Bottom 0.203: v100.08,56.13 100.08,58.8 99.95,58.8 99.95,61.34 99.44,61.85 99.44,86.49 99.95,87 v99.95,89.53
USB14  (via drill 0.51)
  Top 0.203: v117.35,75.44 100.33,58.42 100.33,57.66 98.3,55.88 98.3,53.85 IC3.97 | v124.71,95.76 123.44,97.03 122.43,97.03 120.9,95.5 120.9,93.47 R13.1B
  Top 0.254: R13.1B 121.16,93.22 158.24,93.22 169.42,104.39 171.7,104.39 Q1.1
  Bottom 0.203: v117.35,75.44 121.67,79.76 121.67,85.09 121.41,85.34 121.41,88.9 124.71,92.2 v124.71,95.76
USB15  (via drill 0.51)
  Top 0.254: R14.4B 101.6,91.95 v100.58,91.95 98.81,90.17 98.81,62.23 99.82,61.21 99.82,58.42 97.79,56.39 97.79,53.85 IC3.98 | v172.21,100.84 172.21,99.82 Q2.1 | v167.13,100.84 166.62,100.84 158.5,92.71 124.46,92.71 123.95,92.2 v123.44,92.2
  Bottom 0.254: v167.13,100.84 v172.21,100.84 | v123.44,92.2 100.84,92.2 v100.58,91.95

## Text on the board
Top: U of T - Quantum Optics | Opto-Isolator 6N137 | Rev:A July'05 | In | Out | + | GND | + | - | - | Out | U of T - Quantum Optics | Isolator ADUM1400BRW | Rev:A July'05 | - | + | 5V | 117VAC | In | Out | A | A | A | B | B | C | C | +1.5V | +3.3V | +5V | D | D | 5V | + | - | U of T - Quantum Optics | Opto-Isolator 6N137 | Rev:A July'05 | In | Out | + | + | - | - | Out | U of T - Quantum Optics | Isolator ADUM1400BRW | Rev:A July'05 | - | + | 5V | Dig | I/O | In | Out | 0 | A | A | A | 1 | B | B | 2 | C | C | 3 | D | D | 0 | 4 | 5V | 1 | + | - | 5 | 2 | 3 | 6 | "Squeegee" | 4 | 7 | Aug'05 Rev: A | 5 | A. Steinberg Labs | Com | Analog Inputs | 6 | Quantum Optics Group | 7 | U of T - Physics
Document: "Fast DAC" | +1.5V | +3.3V | +5V | "Slow DAC 1" | "Slow DAC 2" | "Slow DAC 3" | "Slow DAC 4"
Text: "Squeegee" | Generic Controller | A.Stummer, July 2005 | A | 0.008" | 0.012" | 0.008" | 0.004" | 0.025" | "Autorouter Normal Setup.ctl"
